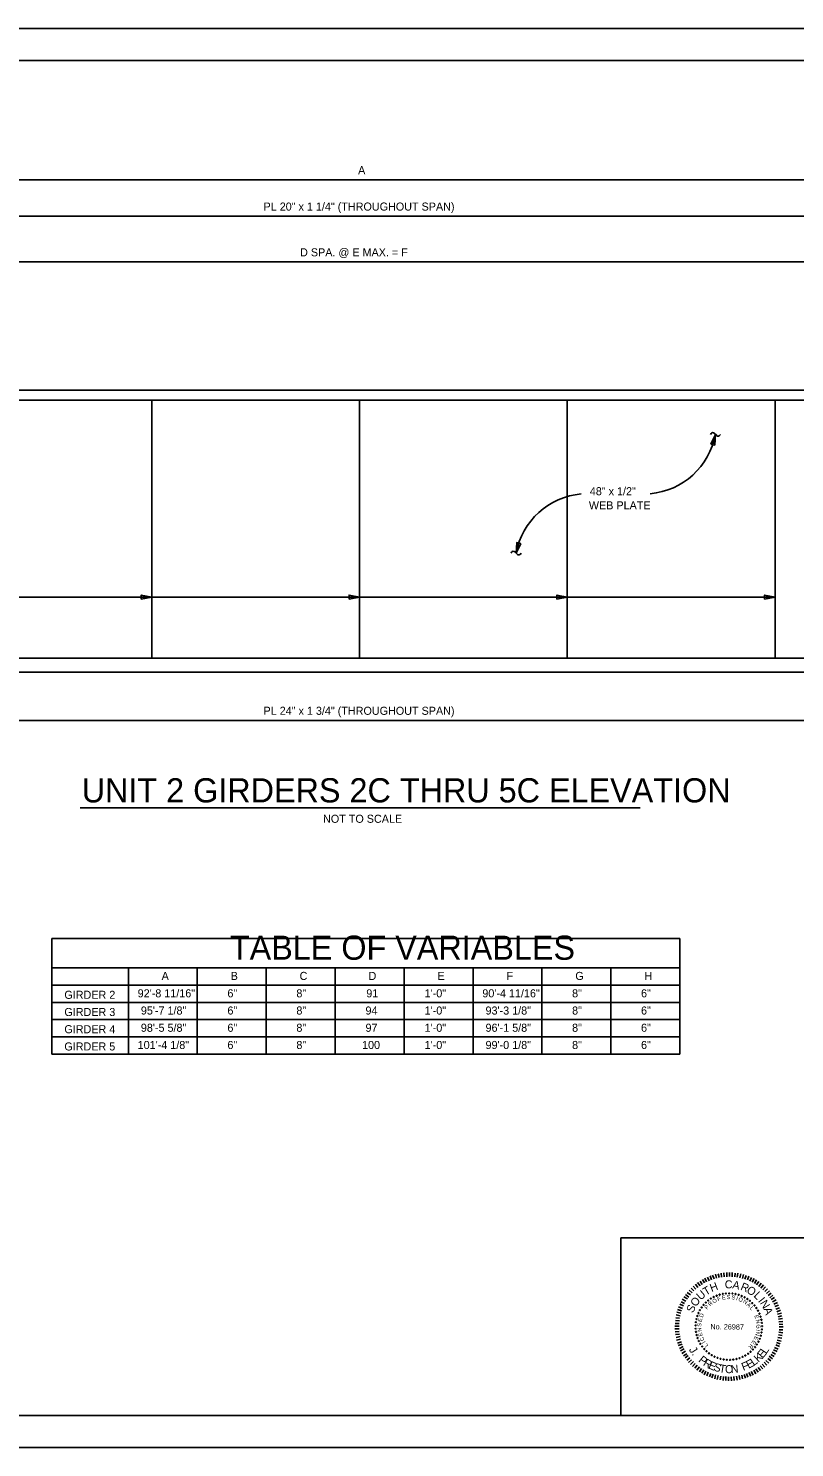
# Model space of a CAD drawing. Extents: x -383 to -161, y -356 to -99.
# Drawn here: x -251.4 to -203.9, y -187.5 to -99.5 of the extents above; entities that cross this region are included whole.
import ezdxf

# ---------------------------------------------------------------- set-up
doc = ezdxf.new("R2010")
doc.units = 0
for name, color, linetype in [('BR_AUTO DIMENSION', 7, 'Continuous'), ('BR_BORDER LINES', 7, 'Continuous'), ('BR_STRUCTURAL STEEL', 7, 'Continuous'), ('BR_TEXT', 7, 'Continuous'), ('Level 31', 7, 'Continuous')]:
    doc.layers.add(name, color=color, linetype=linetype)

msp = doc.modelspace()

# ---------------------------------------------------------------- linework, layer by layer
at = {"layer": 'BR_AUTO DIMENSION'}
for p, q in [((-278.644, -108.876), (-183.048, -108.876)), ((-278.644, -111.134), (-183.048, -111.134)), ((-184.548, -113.971), (-277.144, -113.971)), ((-205.077, -134.756), (-288.61, -134.756)), ((-278.644, -142.397), (-183.048, -142.397)), ((-249.938, -155.913), (-249.938, -163.086)), ((-249.938, -155.913), (-210.987, -155.913)), ((-210.987, -155.913), (-210.987, -163.086)), ((-249.938, -157.747), (-210.987, -157.747)), ((-245.184, -157.747), (-245.184, -163.086)), ((-240.91, -157.747), (-240.91, -163.086)), ((-236.635, -157.747), (-236.635, -163.086)), ((-232.36, -157.747), (-232.36, -163.086)), ((-228.085, -157.747), (-228.085, -163.086)), ((-223.811, -157.747), (-223.811, -163.086)), ((-219.536, -157.747), (-219.536, -163.086)), ((-215.261, -157.747), (-215.261, -163.086)), ((-249.938, -158.815), (-210.987, -158.815)), ((-249.938, -159.882), (-210.987, -159.882)), ((-249.938, -160.95), (-210.987, -160.95)), ((-249.938, -162.018), (-210.987, -162.018)), ((-249.938, -163.086), (-210.987, -163.086))]:
    msp.add_line(p, q, dxfattribs=at)
for points in [[(-209.064, -125.264), (-208.782, -124.665), (-208.822, -125.326)], [(-220.85, -131.432), (-221.133, -132.031), (-221.093, -131.37)], [(-244.381, -134.881), (-243.731, -134.756), (-244.381, -134.631)], [(-231.496, -134.881), (-230.846, -134.756), (-231.496, -134.631)], [(-218.612, -134.881), (-217.962, -134.756), (-218.612, -134.631)], [(-205.727, -134.881), (-205.077, -134.756), (-205.727, -134.631)]]:
    msp.add_lwpolyline(points, close=True, dxfattribs=at)
for centre, start, end in [((-213.206, -123.861), 274.96239, 349.7037), ((-216.709, -132.834), 94.96239, 169.7037)]:
    msp.add_arc(centre, 4.497, start, end, dxfattribs=at)
at = {"layer": 'BR_BORDER LINES'}
for p, q in [((-163.178, -101.489), (-297.843, -101.489)), ((-214.64, -174.489), (-193.18, -174.489)), ((-214.64, -185.489), (-214.64, -174.489)), ((-297.843, -185.489), (-163.178, -185.489))]:
    msp.add_line(p, q, dxfattribs=at)
at = {"layer": 'BR_STRUCTURAL STEEL'}
for p, q in [((-278.644, -121.912), (-183.048, -121.912)), ((-278.644, -122.537), (-183.048, -122.537)), ((-243.731, -122.537), (-243.731, -138.537)), ((-230.846, -122.537), (-230.846, -138.537)), ((-217.962, -122.537), (-217.962, -138.537)), ((-205.077, -122.537), (-205.077, -138.537)), ((-278.644, -138.537), (-183.048, -138.537)), ((-278.644, -139.412), (-183.048, -139.412))]:
    msp.add_line(p, q, dxfattribs=at)
at = {"layer": 'BR_TEXT'}
for p, q in [((-209.042, -124.612), (-209.084, -124.673)), ((-208.7, -124.74), (-208.863, -124.59)), ((-208.467, -124.673), (-208.497, -124.719)), ((-221.448, -132.023), (-221.418, -131.976)), ((-221.215, -131.956), (-221.052, -132.105)), ((-220.873, -132.083), (-220.831, -132.023)), ((-248.166, -147.82), (-213.438, -147.82)), ((-209.02, -177.076), (-209.103, -176.842)), ((-208.861, -177.026), (-208.949, -176.795)), ((-208.717, -176.986), (-208.77, -176.742)), ((-208.552, -176.946), (-208.608, -176.709)), ((-208.394, -176.917), (-208.429, -176.673)), ((-208.236, -176.901), (-208.251, -176.657)), ((-208.077, -176.892), (-208.075, -176.634)), ((-207.909, -176.883), (-207.907, -176.636)), ((-207.741, -176.895), (-207.732, -176.637)), ((-207.58, -176.906), (-207.561, -176.663)), ((-207.426, -176.925), (-207.382, -176.681)), ((-207.265, -176.957), (-207.208, -176.721)), ((-207.1, -176.999), (-207.036, -176.756)), ((-206.953, -177.042), (-206.865, -176.813)), ((-206.795, -177.095), (-206.708, -176.862)), ((-210.228, -177.894), (-210.402, -177.724)), ((-210.11, -177.771), (-210.287, -177.594)), ((-209.993, -177.662), (-210.159, -177.482)), ((-209.861, -177.564), (-210.021, -177.363)), ((-209.726, -177.462), (-209.883, -177.258)), ((-209.602, -177.377), (-209.724, -177.16)), ((-209.461, -177.282), (-209.582, -177.065)), ((-209.323, -177.211), (-209.427, -176.987)), ((-209.175, -177.144), (-209.269, -176.92)), ((-206.652, -177.165), (-206.54, -176.942)), ((-206.508, -177.234), (-206.383, -177.012)), ((-206.358, -177.308), (-206.229, -177.093)), ((-206.225, -177.405), (-206.089, -177.19)), ((-206.091, -177.492), (-205.946, -177.291)), ((-205.962, -177.596), (-205.799, -177.398)), ((-205.836, -177.696), (-205.663, -177.519)), ((-205.723, -177.807), (-205.55, -177.634)), ((-210.756, -178.699), (-210.985, -178.598)), ((-210.686, -178.552), (-210.912, -178.441)), ((-210.617, -178.416), (-210.832, -178.287)), ((-210.519, -178.269), (-210.735, -178.137)), ((-210.432, -178.153), (-210.63, -177.993)), ((-210.328, -178.02), (-210.526, -177.864)), ((-205.611, -177.932), (-205.421, -177.765)), ((-205.502, -178.06), (-205.316, -177.907)), ((-205.407, -178.194), (-205.21, -178.038)), ((-205.319, -178.312), (-205.109, -178.183)), ((-205.231, -178.46), (-205.017, -178.335)), ((-205.16, -178.598), (-204.929, -178.49)), ((-210.996, -179.47), (-211.24, -179.437)), ((-210.954, -179.326), (-211.204, -179.262)), ((-210.925, -179.158), (-211.168, -179.098)), ((-210.876, -179.014), (-211.122, -178.923)), ((-210.826, -178.853), (-211.059, -178.766)), ((-205.089, -178.746), (-204.862, -178.648)), ((-205.022, -178.901), (-204.795, -178.817)), ((-204.968, -179.063), (-204.738, -178.976)), ((-204.928, -179.207), (-204.688, -179.151)), ((-204.895, -179.376), (-204.654, -179.316)), ((-204.862, -179.52), (-204.625, -179.491)), ((-211.029, -180.129), (-211.286, -180.133)), ((-211.034, -179.957), (-211.285, -179.955)), ((-211.026, -179.792), (-211.284, -179.79)), ((-211.02, -180.283), (-211.267, -180.312)), ((-211.015, -179.634), (-211.261, -179.605)), ((-204.841, -180.334), (-204.598, -180.367)), ((-204.836, -179.685), (-204.592, -179.66)), ((-204.833, -180.18), (-204.593, -180.189)), ((-204.831, -179.843), (-204.59, -179.845)), ((-204.822, -180.008), (-204.578, -180.01)), ((-211.004, -180.448), (-211.248, -180.484)), ((-210.964, -180.606), (-211.215, -180.659)), ((-210.938, -180.775), (-211.182, -180.831)), ((-210.891, -180.923), (-211.139, -181.006)), ((-210.845, -181.077), (-211.079, -181.161)), ((-210.777, -181.226), (-211.008, -181.334)), ((-205.11, -181.272), (-204.884, -181.384)), ((-205.04, -181.125), (-204.814, -181.213)), ((-204.984, -180.971), (-204.755, -181.059)), ((-204.942, -180.824), (-204.702, -180.885)), ((-204.906, -180.656), (-204.666, -180.713)), ((-204.87, -180.499), (-204.634, -180.538)), ((-210.71, -181.37), (-210.937, -181.489)), ((-210.642, -181.519), (-210.859, -181.644)), ((-210.547, -181.667), (-210.765, -181.792)), ((-210.462, -181.784), (-210.663, -181.93)), ((-210.361, -181.919), (-210.561, -182.075)), ((-210.262, -182.054), (-210.439, -182.217)), ((-210.146, -182.158), (-210.326, -182.338)), ((-205.645, -182.092), (-205.458, -182.258)), ((-205.535, -181.959), (-205.351, -182.118)), ((-205.437, -181.826), (-205.243, -181.975)), ((-205.347, -181.71), (-205.139, -181.839)), ((-205.257, -181.563), (-205.045, -181.692)), ((-205.183, -181.416), (-204.954, -181.538)), ((-210.031, -182.279), (-210.2, -182.463)), ((-209.901, -182.383), (-210.064, -182.57)), ((-209.768, -182.487), (-209.928, -182.678)), ((-209.645, -182.574), (-209.77, -182.782)), ((-209.505, -182.664), (-209.63, -182.879)), ((-209.368, -182.744), (-209.477, -182.967)), ((-209.221, -182.814), (-209.319, -183.037)), ((-209.068, -182.884), (-209.155, -183.11)), ((-208.91, -182.933), (-209.001, -183.166)), ((-208.766, -182.983), (-208.823, -183.219)), ((-208.602, -183.011), (-208.662, -183.258)), ((-207.315, -183.022), (-207.262, -183.27)), ((-207.15, -182.996), (-207.09, -183.233)), ((-207.002, -182.949), (-206.918, -183.183)), ((-206.843, -182.902), (-206.759, -183.13)), ((-206.699, -182.835), (-206.591, -183.059)), ((-206.554, -182.768), (-206.432, -182.992)), ((-206.402, -182.69), (-206.277, -182.907)), ((-206.268, -182.602), (-206.135, -182.812)), ((-206.133, -182.517), (-205.99, -182.71)), ((-206.002, -182.415), (-205.842, -182.605)), ((-205.874, -182.313), (-205.704, -182.5)), ((-205.76, -182.194), (-205.589, -182.377)), ((-208.444, -183.057), (-208.484, -183.29)), ((-208.287, -183.076), (-208.306, -183.323)), ((-208.129, -183.087), (-208.131, -183.335)), ((-207.961, -183.099), (-207.963, -183.343)), ((-207.792, -183.09), (-207.787, -183.338)), ((-207.631, -183.081), (-207.616, -183.329)), ((-207.476, -183.065), (-207.437, -183.299))]:
    msp.add_line(p, q, dxfattribs=at)
for centre, radius, start, end in [((-208.944, -124.665), 0.111, 43.45189, 151.73747), ((-208.606, -124.658), 0.125, 221.00704, 330.80591), ((-221.308, -132.037), 0.125, 41.00704, 150.80591), ((-220.971, -132.03), 0.111, 223.45189, 331.73747), ((-209.511, -178.639), 0.028, 49.37299, 229.37299), ((-209.511, -178.639), 0.028, 229.37299, 49.37299), ((-209.373, -178.495), 0.028, 43.83453, 223.83453), ((-209.373, -178.495), 0.028, 223.83453, 43.83453), ((-209.223, -178.364), 0.028, 38.29606, 218.29606), ((-209.223, -178.364), 0.028, 218.29606, 38.29606), ((-209.06, -178.248), 0.028, 32.7576, 212.7576), ((-209.06, -178.248), 0.028, 212.7576, 32.7576), ((-208.887, -178.149), 0.028, 27.21914, 207.21914), ((-208.887, -178.149), 0.028, 207.21914, 27.21914), ((-208.706, -178.067), 0.028, 21.68068, 201.68068), ((-208.706, -178.067), 0.028, 201.68068, 21.68068), ((-208.517, -178.003), 0.028, 16.14222, 196.14222), ((-208.517, -178.003), 0.028, 196.14222, 16.14222), ((-208.323, -177.957), 0.028, 10.60376, 190.60376), ((-208.323, -177.957), 0.028, 190.60376, 10.60376), ((-208.126, -177.93), 0.028, 5.06529, 185.06529), ((-208.126, -177.93), 0.028, 185.06529, 5.06529), ((-207.926, -177.923), 0.028, 359.52683, 179.52683), ((-207.926, -177.923), 0.028, 179.52683, 359.52683), ((-207.727, -177.934), 0.028, 173.98837, 353.98837), ((-207.727, -177.934), 0.028, 353.98837, 173.98837), ((-207.531, -177.965), 0.028, 168.44991, 348.44991), ((-207.531, -177.965), 0.028, 348.44991, 168.44991), ((-207.338, -178.015), 0.028, 162.91145, 342.91145), ((-207.338, -178.015), 0.028, 342.91145, 162.91145), ((-207.15, -178.083), 0.028, 157.37299, 337.37299), ((-207.15, -178.083), 0.028, 337.37299, 157.37299), ((-206.97, -178.169), 0.028, 151.83453, 331.83453), ((-206.97, -178.169), 0.028, 331.83453, 151.83453), ((-206.8, -178.272), 0.028, 146.29606, 326.29606), ((-206.8, -178.272), 0.028, 326.29606, 146.29606), ((-206.639, -178.39), 0.028, 140.7576, 320.7576), ((-206.639, -178.39), 0.028, 320.7576, 140.7576), ((-206.492, -178.524), 0.028, 135.21914, 315.21914), ((-206.492, -178.524), 0.028, 315.21914, 135.21914), ((-209.957, -179.52), 0.028, 77.06529, 257.06529), ((-209.957, -179.52), 0.028, 257.06529, 77.06529), ((-209.903, -179.328), 0.028, 71.52683, 251.52683), ((-209.903, -179.328), 0.028, 251.52683, 71.52683), ((-209.83, -179.142), 0.028, 65.98837, 245.98837), ((-209.83, -179.142), 0.028, 245.98837, 65.98837), ((-209.74, -178.964), 0.028, 60.44991, 240.44991), ((-209.74, -178.964), 0.028, 240.44991, 60.44991), ((-209.633, -178.796), 0.028, 54.91145, 234.91145), ((-209.633, -178.796), 0.028, 234.91145, 54.91145), ((-206.357, -178.671), 0.028, 129.68068, 309.68068), ((-206.357, -178.671), 0.028, 309.68068, 129.68068), ((-206.238, -178.831), 0.028, 124.14222, 304.14222), ((-206.238, -178.831), 0.028, 304.14222, 124.14222), ((-206.135, -179.001), 0.028, 118.60376, 298.60376), ((-206.135, -179.001), 0.028, 298.60376, 118.60376), ((-206.048, -179.181), 0.028, 113.06529, 293.06529), ((-206.048, -179.181), 0.028, 293.06529, 113.06529), ((-205.979, -179.368), 0.028, 107.52683, 287.52683), ((-205.979, -179.368), 0.028, 287.52683, 107.52683), ((-210.009, -179.914), 0.028, 88.14222, 268.14222), ((-210.006, -180.114), 0.028, 93.68068, 273.68068), ((-209.993, -179.716), 0.028, 82.60376, 262.60376), ((-209.984, -180.312), 0.028, 99.21914, 279.21914), ((-210.009, -179.914), 0.028, 268.14222, 88.14222), ((-210.006, -180.114), 0.028, 273.68068, 93.68068), ((-209.993, -179.716), 0.028, 262.60376, 82.60376), ((-209.984, -180.312), 0.028, 279.21914, 99.21914), ((-205.929, -179.561), 0.028, 101.98837, 281.98837), ((-205.918, -180.353), 0.028, 79.83453, 259.83453), ((-205.929, -179.561), 0.028, 281.98837, 101.98837), ((-205.897, -179.758), 0.028, 96.44991, 276.44991), ((-205.918, -180.353), 0.028, 259.83453, 79.83453), ((-205.892, -180.156), 0.028, 85.37299, 265.37299), ((-205.885, -179.957), 0.028, 90.91145, 270.91145), ((-205.897, -179.758), 0.028, 276.44991, 96.44991), ((-205.892, -180.156), 0.028, 265.37299, 85.37299), ((-205.885, -179.957), 0.028, 270.91145, 90.91145), ((-209.943, -180.507), 0.028, 104.7576, 284.7576), ((-209.943, -180.507), 0.028, 284.7576, 104.7576), ((-209.884, -180.697), 0.028, 110.29606, 290.29606), ((-209.884, -180.697), 0.028, 290.29606, 110.29606), ((-209.806, -180.881), 0.028, 115.83453, 295.83453), ((-209.806, -180.881), 0.028, 295.83453, 115.83453), ((-209.711, -181.056), 0.028, 121.37299, 301.37299), ((-209.711, -181.056), 0.028, 301.37299, 121.37299), ((-209.599, -181.221), 0.028, 126.91145, 306.91145), ((-209.599, -181.221), 0.028, 306.91145, 126.91145), ((-206.321, -181.255), 0.028, 52.14222, 232.14222), ((-206.321, -181.255), 0.028, 232.14222, 52.14222), ((-206.207, -181.092), 0.028, 57.68068, 237.68068), ((-206.207, -181.092), 0.028, 237.68068, 57.68068), ((-206.108, -180.918), 0.028, 63.21914, 243.21914), ((-206.108, -180.918), 0.028, 243.21914, 63.21914), ((-206.026, -180.737), 0.028, 68.7576, 248.7576), ((-206.026, -180.737), 0.028, 248.7576, 68.7576), ((-205.963, -180.548), 0.028, 74.29606, 254.29606), ((-205.963, -180.548), 0.028, 254.29606, 74.29606), ((-209.472, -181.375), 0.028, 132.44991, 312.44991), ((-209.472, -181.375), 0.028, 312.44991, 132.44991), ((-209.331, -181.515), 0.028, 137.98837, 317.98837), ((-209.331, -181.515), 0.028, 317.98837, 137.98837), ((-209.177, -181.642), 0.028, 143.52683, 323.52683), ((-209.177, -181.642), 0.028, 323.52683, 143.52683), ((-209.011, -181.753), 0.028, 149.06529, 329.06529), ((-209.011, -181.753), 0.028, 329.06529, 149.06529), ((-208.836, -181.847), 0.028, 154.60376, 334.60376), ((-208.836, -181.847), 0.028, 334.60376, 154.60376), ((-208.652, -181.924), 0.028, 160.14222, 340.14222), ((-208.652, -181.924), 0.028, 340.14222, 160.14222), ((-208.462, -181.983), 0.028, 165.68068, 345.68068), ((-208.462, -181.983), 0.028, 345.68068, 165.68068), ((-208.267, -182.023), 0.028, 171.21914, 351.21914), ((-208.267, -182.023), 0.028, 351.21914, 171.21914), ((-208.068, -182.045), 0.028, 356.7576, 176.7576), ((-208.068, -182.045), 0.028, 176.7576, 356.7576), ((-207.869, -182.047), 0.028, 2.29606, 182.29606), ((-207.869, -182.047), 0.028, 182.29606, 2.29606), ((-207.67, -182.029), 0.028, 7.83453, 187.83453), ((-207.67, -182.029), 0.028, 187.83453, 7.83453), ((-207.474, -181.993), 0.028, 13.37299, 193.37299), ((-207.474, -181.993), 0.028, 193.37299, 13.37299), ((-207.283, -181.938), 0.028, 18.91145, 198.91145), ((-207.283, -181.938), 0.028, 198.91145, 18.91145), ((-207.098, -181.865), 0.028, 24.44991, 204.44991), ((-207.098, -181.865), 0.028, 204.44991, 24.44991), ((-206.92, -181.774), 0.028, 29.98837, 209.98837), ((-206.92, -181.774), 0.028, 209.98837, 29.98837), ((-206.752, -181.667), 0.028, 35.52683, 215.52683), ((-206.752, -181.667), 0.028, 215.52683, 35.52683), ((-206.596, -181.543), 0.028, 41.06529, 221.06529), ((-206.596, -181.543), 0.028, 221.06529, 41.06529), ((-206.452, -181.406), 0.028, 46.60376, 226.60376), ((-206.452, -181.406), 0.028, 226.60376, 46.60376)]:
    msp.add_arc(centre, radius, start, end, dxfattribs=at)
at = {"layer": 'Level 31'}
msp.add_lwpolyline([(-305.176, -187.489), (-161.176, -187.489), (-161.176, -99.489), (-305.176, -99.489)], close=True, dxfattribs=at)

# ---------------------------------------------------------------- texts
at = {"layer": 'BR_AUTO DIMENSION'}
for s, p in [('A', (-230.936, -108.53)), ('PL 20" x 1 1/4" (THROUGHOUT SPAN)', (-236.8, -110.788)), ('D SPA. @ E MAX. = F', (-234.534, -113.625)), ('48" x 1/2" ', (-216.567, -128.437)), ('WEB PLATE', (-216.626, -129.312)), ('PL 24" x 1 3/4" (THROUGHOUT SPAN)', (-236.8, -142.051))]:
    msp.add_text(s, height=0.5, rotation=360, dxfattribs=at).set_placement(p)
at = {"layer": 'BR_TEXT'}
for s, height, p in [('UNIT 2 GIRDERS 2C THRU 5C ELEVATION', 1.5, (-248.076, -147.483)), ('NOT TO SCALE', 0.5, (-233.109, -148.747)), ('TABLE OF VARIABLES', 1.5, (-238.887, -157.24))]:
    msp.add_text(s, height=height, dxfattribs=at).set_placement(p)
for s, height, rotation, p in [('A', 0.5, 360, (-243.12, -158.492)), ('B', 0.5, 360, (-238.837, -158.492)), ('C', 0.5, 360, (-234.563, -158.492)), ('D', 0.5, 360, (-230.29, -158.492)), ('E', 0.5, 360, (-226.012, -158.492)), ('F', 0.5, 360, (-221.729, -158.492)), ('G', 0.5, 360, (-217.464, -158.492)), ('H', 0.5, 360, (-213.18, -158.492)), ('GIRDER 2', 0.5, 360, (-249.151, -159.661)), ('92\'-8 11/16"', 0.5, 360, (-244.605, -159.57)), ('6"', 0.5, 360, (-239.039, -159.57)), ('8"', 0.5, 360, (-234.764, -159.57)), ('91', 0.5, 360, (-230.427, -159.57)), ('1\'-0"', 0.5, 360, (-226.81, -159.57)), ('90\'-4 11/16"', 0.5, 360, (-223.232, -159.57)), ('8"', 0.5, 360, (-217.666, -159.57)), ('6"', 0.5, 360, (-213.391, -159.57)), ('95\'-7 1/8"', 0.5, 360, (-244.407, -160.637)), ('6"', 0.5, 360, (-239.039, -160.637)), ('8"', 0.5, 360, (-234.764, -160.637)), ('94', 0.5, 360, (-230.477, -160.637)), ('1\'-0"', 0.5, 360, (-226.81, -160.637)), ('93\'-3 1/8"', 0.5, 360, (-223.033, -160.637)), ('8"', 0.5, 360, (-217.666, -160.637)), ('6"', 0.5, 360, (-213.391, -160.637)), ('GIRDER 3', 0.5, 360, (-249.151, -160.729)), ('GIRDER 4', 0.5, 360, (-249.151, -161.796)), ('98\'-5 5/8"', 0.5, 360, (-244.407, -161.705)), ('6"', 0.5, 360, (-239.039, -161.705)), ('8"', 0.5, 360, (-234.764, -161.705)), ('97', 0.5, 360, (-230.477, -161.705)), ('1\'-0"', 0.5, 360, (-226.81, -161.705)), ('96\'-1 5/8"', 0.5, 360, (-223.033, -161.705)), ('8"', 0.5, 360, (-217.666, -161.705)), ('6"', 0.5, 360, (-213.391, -161.705)), ('GIRDER 5', 0.5, 360, (-249.151, -162.864)), ('101\'-4 1/8"', 0.5, 360, (-244.605, -162.773)), ('6"', 0.5, 360, (-239.039, -162.773)), ('8"', 0.5, 360, (-234.764, -162.773)), ('100', 0.5, 360, (-230.691, -162.773)), ('1\'-0"', 0.5, 360, (-226.81, -162.773)), ('99\'-0 1/8"', 0.5, 360, (-223.033, -162.773)), ('8"', 0.5, 360, (-217.666, -162.773)), ('6"', 0.5, 360, (-213.391, -162.773)), ('U', 0.496, 40.80225, (-209.694, -178.375)), ('T', 0.496, 30.49921, (-209.37, -178.076)), ('H', 0.496, 20.36371, (-209.018, -177.846)), ('C', 0.496, 359.54822, (-208.2, -177.612)), ('A', 0.496, 348.19813, (-207.755, -177.609)), ('R', 0.496, 337.43439, (-207.262, -177.689)), ('O', 0.496, 326.58689, (-206.893, -177.836)), ('S', 0.496, 63.25114, (-210.174, -179.173)), ('O', 0.496, 52.0267, (-209.993, -178.79)), ('R', 0.249, 40.39491, (-209.107, -178.737)), ('O', 0.249, 30.84774, (-208.882, -178.561)), ('F', 0.249, 20.61271, (-208.613, -178.417)), ('E', 0.249, 11.41035, (-208.352, -178.33)), ('S', 0.249, 2.20798, (-208.081, -178.286)), ('S', 0.249, 352.66081, (-207.796, -178.287)), ('I', 0.249, 343.11363, (-207.515, -178.335)), ('O', 0.249, 338.43918, (-207.381, -178.376)), ('N', 0.249, 328.20415, (-207.103, -178.501)), ('A', 0.249, 318.65698, (-206.867, -178.662)), ('L', 0.496, 315.94879, (-206.442, -178.107)), ('I', 0.496, 308.66128, (-206.157, -178.404)), ('N', 0.496, 300.70365, (-206.035, -178.521)), ('E', 0.249, 78.23881, (-209.633, -179.715)), ('D', 0.249, 69.03644, (-209.567, -179.448)), ('P', 0.249, 49.94209, (-209.299, -178.947)), ('L', 0.249, 309.45461, (-206.668, -178.851)), ('E', 0.249, 291.049, (-206.372, -179.312)), ('A', 0.496, 289.47921, (-205.798, -178.894)), ('S', 0.249, 87.78598, (-209.656, -179.999)), ('N', 0.249, 97.33316, (-209.632, -180.283)), ('E', 0.249, 106.53552, (-209.564, -180.549)), ('No. 26987', 0.327, 359.52683, (-209.092, -180.153)), ('N', 0.249, 257.73391, (-206.256, -180.287)), ('N', 0.249, 281.84664, (-206.283, -179.572)), ('I', 0.249, 262.40836, (-206.238, -180.149)), ('G', 0.249, 272.29946, (-206.237, -179.853)), ('J', 0.494, 302.95589, (-210.441, -181.421)), ('C', 0.249, 116.42662, (-209.444, -180.819)), ('I', 0.249, 121.10107, (-209.372, -180.939)), ('L', 0.249, 129.95951, (-209.209, -181.147)), ('R', 0.249, 229.78201, (-206.591, -181.044)), ('E', 0.249, 238.98437, (-206.44, -180.814)), ('E', 0.249, 248.18673, (-206.328, -180.563)), ('.', 0.494, 309.39736, (-210.264, -181.693)), ('P', 0.494, 321.10348, (-209.871, -182.13)), ('R', 0.494, 328.53593, (-209.578, -182.362)), ('E', 0.494, 335.96839, (-209.257, -182.555)), ('F', 0.494, 21.12057, (-207.05, -182.735)), ('E', 0.494, 28.1814, (-206.719, -182.605)), ('L', 0.494, 35.24223, (-206.407, -182.436)), ('K', 0.494, 42.30307, (-206.118, -182.229)), ('E', 0.494, 49.3639, (-205.857, -181.989)), ('L', 0.494, 56.42474, (-205.627, -181.718)), ('S', 0.494, 343.02922, (-208.932, -182.698)), ('T', 0.494, 350.46168, (-208.573, -182.804)), ('O', 0.494, 358.14189, (-208.192, -182.863)), ('N', 0.494, 5.82209, (-207.805, -182.872))]:
    msp.add_text(s, height=height, rotation=rotation, dxfattribs=at).set_placement(p)

doc.saveas('drawing.dxf')
